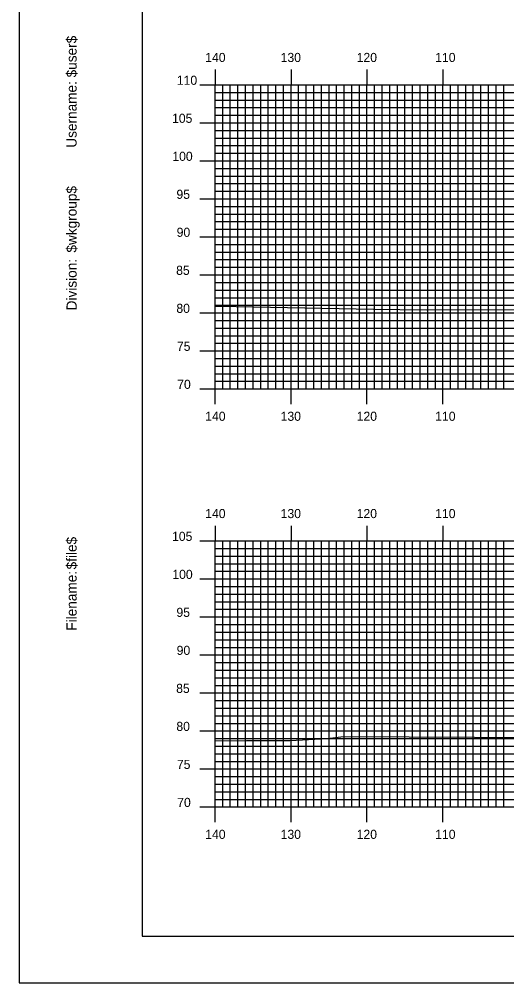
# Model space of a CAD drawing. Extents: x 1758643 to 1758986, y 442591 to 442811.
# Drawn here: x 1758642.9 to 1758707.1, y 442590.5 to 442717.3 of the extents above; entities that cross this region are included whole.
import ezdxf

# ---------------------------------------------------------------- set-up
doc = ezdxf.new("R2010")
doc.units = 0
for name, color, linetype in [('BORDER', 7, 'Continuous'), ('H_V ANNOTATION', 7, 'Continuous'), ('MAJOR', 7, 'Continuous'), ('MINOR', 7, 'Continuous'), ('PLOT BOUNDARY', 7, 'Continuous'), ('S_Roadway_Centerline', 7, 'Continuous')]:
    doc.layers.add(name, color=color, linetype=linetype)

msp = doc.modelspace()

# ---------------------------------------------------------------- linework, layer by layer
at = {"layer": 'BORDER'}
msp.add_lwpolyline([(1758659.05, 442596.67), (1758979.05, 442596.67), (1758979.05, 442806.67), (1758659.05, 442806.67)], close=True, dxfattribs=at)
at = {"layer": 'MAJOR'}
for p, q in [((1758668.65, 442710.67), (1758668.65, 442708.67)), ((1758678.65, 442710.67), (1758678.65, 442708.67)), ((1758688.65, 442710.67), (1758688.65, 442708.67)), ((1758698.65, 442710.67), (1758698.65, 442708.67)), ((1758666.64, 442708.67), (1758668.65, 442708.67)), ((1758668.65, 442708.67), (1758948.65, 442708.67)), ((1758668.65, 442668.67), (1758668.65, 442708.67)), ((1758668.65, 442668.67), (1758668.65, 442708.67)), ((1758668.65, 442708.67), (1758948.65, 442708.67)), ((1758678.65, 442668.67), (1758678.65, 442708.67)), ((1758688.65, 442668.67), (1758688.65, 442708.67)), ((1758698.65, 442668.67), (1758698.65, 442708.67)), ((1758666.64, 442703.67), (1758668.65, 442703.67)), ((1758668.65, 442703.67), (1758948.65, 442703.67)), ((1758666.64, 442698.67), (1758668.65, 442698.67)), ((1758668.65, 442698.67), (1758948.65, 442698.67)), ((1758666.64, 442693.67), (1758668.65, 442693.67)), ((1758668.65, 442693.67), (1758948.65, 442693.67)), ((1758666.64, 442688.67), (1758668.65, 442688.67)), ((1758668.65, 442688.67), (1758948.65, 442688.67)), ((1758666.64, 442683.67), (1758668.65, 442683.67)), ((1758668.65, 442683.67), (1758948.65, 442683.67)), ((1758666.64, 442678.67), (1758668.65, 442678.67)), ((1758668.65, 442678.67), (1758948.65, 442678.67)), ((1758666.64, 442673.67), (1758668.65, 442673.67)), ((1758668.65, 442673.67), (1758948.65, 442673.67)), ((1758666.64, 442668.67), (1758668.65, 442668.67)), ((1758668.65, 442668.67), (1758948.65, 442668.67)), ((1758668.65, 442668.67), (1758948.65, 442668.67)), ((1758668.65, 442666.66), (1758668.65, 442668.67)), ((1758678.65, 442666.66), (1758678.65, 442668.67)), ((1758688.65, 442666.66), (1758688.65, 442668.67)), ((1758698.65, 442666.66), (1758698.65, 442668.67)), ((1758668.65, 442650.67), (1758668.65, 442648.67)), ((1758678.65, 442650.67), (1758678.65, 442648.67)), ((1758688.65, 442650.67), (1758688.65, 442648.67)), ((1758698.65, 442650.67), (1758698.65, 442648.67)), ((1758666.64, 442648.67), (1758668.65, 442648.67)), ((1758668.65, 442648.67), (1758948.65, 442648.67)), ((1758668.65, 442613.67), (1758668.65, 442648.67)), ((1758668.65, 442613.67), (1758668.65, 442648.67)), ((1758668.65, 442648.67), (1758948.65, 442648.67)), ((1758678.65, 442613.67), (1758678.65, 442648.67)), ((1758688.65, 442613.67), (1758688.65, 442648.67)), ((1758698.65, 442613.67), (1758698.65, 442648.67)), ((1758666.64, 442643.67), (1758668.65, 442643.67)), ((1758668.65, 442643.67), (1758948.65, 442643.67)), ((1758666.64, 442638.67), (1758668.65, 442638.67)), ((1758668.65, 442638.67), (1758948.65, 442638.67)), ((1758666.64, 442633.67), (1758668.65, 442633.67)), ((1758668.65, 442633.67), (1758948.65, 442633.67)), ((1758666.64, 442628.67), (1758668.65, 442628.67)), ((1758668.65, 442628.67), (1758948.65, 442628.67)), ((1758666.64, 442623.67), (1758668.65, 442623.67)), ((1758668.65, 442623.67), (1758948.65, 442623.67)), ((1758666.64, 442618.67), (1758668.65, 442618.67)), ((1758668.65, 442618.67), (1758948.65, 442618.67)), ((1758666.64, 442613.67), (1758668.65, 442613.67)), ((1758668.65, 442613.67), (1758948.65, 442613.67)), ((1758668.65, 442613.67), (1758948.65, 442613.67)), ((1758668.65, 442611.66), (1758668.65, 442613.67)), ((1758678.65, 442611.66), (1758678.65, 442613.67)), ((1758688.65, 442611.66), (1758688.65, 442613.67)), ((1758698.65, 442611.66), (1758698.65, 442613.67))]:
    msp.add_line(p, q, dxfattribs=at)
at = {"layer": 'MINOR'}
for p, q in [((1758669.65, 442668.67), (1758669.65, 442708.67)), ((1758670.65, 442668.67), (1758670.65, 442708.67)), ((1758671.65, 442668.67), (1758671.65, 442708.67)), ((1758672.65, 442668.67), (1758672.65, 442708.67)), ((1758673.65, 442668.67), (1758673.65, 442708.67)), ((1758674.65, 442668.67), (1758674.65, 442708.67)), ((1758675.65, 442668.67), (1758675.65, 442708.67)), ((1758676.65, 442668.67), (1758676.65, 442708.67)), ((1758677.65, 442668.67), (1758677.65, 442708.67)), ((1758679.65, 442668.67), (1758679.65, 442708.67)), ((1758680.65, 442668.67), (1758680.65, 442708.67)), ((1758681.65, 442668.67), (1758681.65, 442708.67)), ((1758682.65, 442668.67), (1758682.65, 442708.67)), ((1758683.65, 442668.67), (1758683.65, 442708.67)), ((1758684.65, 442668.67), (1758684.65, 442708.67)), ((1758685.65, 442668.67), (1758685.65, 442708.67)), ((1758686.65, 442668.67), (1758686.65, 442708.67)), ((1758687.65, 442668.67), (1758687.65, 442708.67)), ((1758689.65, 442668.67), (1758689.65, 442708.67)), ((1758690.65, 442668.67), (1758690.65, 442708.67)), ((1758691.65, 442668.67), (1758691.65, 442708.67)), ((1758692.65, 442668.67), (1758692.65, 442708.67)), ((1758693.65, 442668.67), (1758693.65, 442708.67)), ((1758694.65, 442668.67), (1758694.65, 442708.67)), ((1758695.65, 442668.67), (1758695.65, 442708.67)), ((1758696.65, 442668.67), (1758696.65, 442708.67)), ((1758697.65, 442668.67), (1758697.65, 442708.67)), ((1758699.65, 442668.67), (1758699.65, 442708.67)), ((1758700.65, 442668.67), (1758700.65, 442708.67)), ((1758701.65, 442668.67), (1758701.65, 442708.67)), ((1758702.65, 442668.67), (1758702.65, 442708.67)), ((1758703.65, 442668.67), (1758703.65, 442708.67)), ((1758704.65, 442668.67), (1758704.65, 442708.67)), ((1758705.65, 442668.67), (1758705.65, 442708.67)), ((1758706.65, 442668.67), (1758706.65, 442708.67)), ((1758668.65, 442707.67), (1758948.65, 442707.67)), ((1758668.65, 442707.67), (1758670.65, 442707.67)), ((1758668.65, 442706.67), (1758948.65, 442706.67)), ((1758668.65, 442706.67), (1758670.65, 442706.67)), ((1758668.65, 442705.67), (1758948.65, 442705.67)), ((1758668.65, 442705.67), (1758670.65, 442705.67)), ((1758668.65, 442704.67), (1758948.65, 442704.67)), ((1758668.65, 442704.67), (1758670.65, 442704.67)), ((1758668.65, 442702.67), (1758948.65, 442702.67)), ((1758668.65, 442702.67), (1758670.65, 442702.67)), ((1758668.65, 442701.67), (1758948.65, 442701.67)), ((1758668.65, 442701.67), (1758670.65, 442701.67)), ((1758668.65, 442700.67), (1758948.65, 442700.67)), ((1758668.65, 442700.67), (1758670.65, 442700.67)), ((1758668.65, 442699.67), (1758948.65, 442699.67)), ((1758668.65, 442699.67), (1758670.65, 442699.67)), ((1758668.65, 442697.67), (1758948.65, 442697.67)), ((1758668.65, 442697.67), (1758670.65, 442697.67)), ((1758668.65, 442696.67), (1758948.65, 442696.67)), ((1758668.65, 442696.67), (1758670.65, 442696.67)), ((1758668.65, 442695.67), (1758948.65, 442695.67)), ((1758668.65, 442695.67), (1758670.65, 442695.67)), ((1758668.65, 442694.67), (1758948.65, 442694.67)), ((1758668.65, 442694.67), (1758670.65, 442694.67)), ((1758668.65, 442692.67), (1758948.65, 442692.67)), ((1758668.65, 442692.67), (1758670.65, 442692.67)), ((1758668.65, 442691.67), (1758948.65, 442691.67)), ((1758668.65, 442691.67), (1758670.65, 442691.67)), ((1758668.65, 442690.67), (1758948.65, 442690.67)), ((1758668.65, 442690.67), (1758670.65, 442690.67)), ((1758668.65, 442689.67), (1758948.65, 442689.67)), ((1758668.65, 442689.67), (1758670.65, 442689.67)), ((1758668.65, 442687.67), (1758948.65, 442687.67)), ((1758668.65, 442687.67), (1758670.65, 442687.67)), ((1758668.65, 442686.67), (1758948.65, 442686.67)), ((1758668.65, 442686.67), (1758670.65, 442686.67)), ((1758668.65, 442685.67), (1758948.65, 442685.67)), ((1758668.65, 442685.67), (1758670.65, 442685.67)), ((1758668.65, 442684.67), (1758948.65, 442684.67)), ((1758668.65, 442684.67), (1758670.65, 442684.67)), ((1758668.65, 442682.67), (1758948.65, 442682.67)), ((1758668.65, 442682.67), (1758670.65, 442682.67)), ((1758668.65, 442681.67), (1758948.65, 442681.67)), ((1758668.65, 442681.67), (1758670.65, 442681.67)), ((1758668.65, 442680.67), (1758948.65, 442680.67)), ((1758668.65, 442680.67), (1758670.65, 442680.67)), ((1758668.65, 442679.67), (1758948.65, 442679.67)), ((1758668.65, 442679.67), (1758670.65, 442679.67)), ((1758668.65, 442677.67), (1758948.65, 442677.67)), ((1758668.65, 442677.67), (1758670.65, 442677.67)), ((1758668.65, 442676.67), (1758948.65, 442676.67)), ((1758668.65, 442676.67), (1758670.65, 442676.67)), ((1758668.65, 442675.67), (1758948.65, 442675.67)), ((1758668.65, 442675.67), (1758670.65, 442675.67)), ((1758668.65, 442674.67), (1758948.65, 442674.67)), ((1758668.65, 442674.67), (1758670.65, 442674.67)), ((1758668.65, 442672.67), (1758948.65, 442672.67)), ((1758668.65, 442672.67), (1758670.65, 442672.67)), ((1758668.65, 442671.67), (1758948.65, 442671.67)), ((1758668.65, 442671.67), (1758670.65, 442671.67)), ((1758668.65, 442670.67), (1758948.65, 442670.67)), ((1758668.65, 442670.67), (1758670.65, 442670.67)), ((1758668.65, 442669.67), (1758948.65, 442669.67)), ((1758668.65, 442669.67), (1758670.65, 442669.67)), ((1758669.65, 442613.67), (1758669.65, 442648.67)), ((1758670.65, 442613.67), (1758670.65, 442648.67)), ((1758671.65, 442613.67), (1758671.65, 442648.67)), ((1758672.65, 442613.67), (1758672.65, 442648.67)), ((1758673.65, 442613.67), (1758673.65, 442648.67)), ((1758674.65, 442613.67), (1758674.65, 442648.67)), ((1758675.65, 442613.67), (1758675.65, 442648.67)), ((1758676.65, 442613.67), (1758676.65, 442648.67)), ((1758677.65, 442613.67), (1758677.65, 442648.67)), ((1758679.65, 442613.67), (1758679.65, 442648.67)), ((1758680.65, 442613.67), (1758680.65, 442648.67)), ((1758681.65, 442613.67), (1758681.65, 442648.67)), ((1758682.65, 442613.67), (1758682.65, 442648.67)), ((1758683.65, 442613.67), (1758683.65, 442648.67)), ((1758684.65, 442613.67), (1758684.65, 442648.67)), ((1758685.65, 442613.67), (1758685.65, 442648.67)), ((1758686.65, 442613.67), (1758686.65, 442648.67)), ((1758687.65, 442613.67), (1758687.65, 442648.67)), ((1758689.65, 442613.67), (1758689.65, 442648.67)), ((1758690.65, 442613.67), (1758690.65, 442648.67)), ((1758691.65, 442613.67), (1758691.65, 442648.67)), ((1758692.65, 442613.67), (1758692.65, 442648.67)), ((1758693.65, 442613.67), (1758693.65, 442648.67)), ((1758694.65, 442613.67), (1758694.65, 442648.67)), ((1758695.65, 442613.67), (1758695.65, 442648.67)), ((1758696.65, 442613.67), (1758696.65, 442648.67)), ((1758697.65, 442613.67), (1758697.65, 442648.67)), ((1758699.65, 442613.67), (1758699.65, 442648.67)), ((1758700.65, 442613.67), (1758700.65, 442648.67)), ((1758701.65, 442613.67), (1758701.65, 442648.67)), ((1758702.65, 442613.67), (1758702.65, 442648.67)), ((1758703.65, 442613.67), (1758703.65, 442648.67)), ((1758704.65, 442613.67), (1758704.65, 442648.67)), ((1758705.65, 442613.67), (1758705.65, 442648.67)), ((1758706.65, 442613.67), (1758706.65, 442648.67)), ((1758668.65, 442647.67), (1758948.65, 442647.67)), ((1758668.65, 442647.67), (1758670.65, 442647.67)), ((1758668.65, 442646.67), (1758948.65, 442646.67)), ((1758668.65, 442646.67), (1758670.65, 442646.67)), ((1758668.65, 442645.67), (1758948.65, 442645.67)), ((1758668.65, 442645.67), (1758670.65, 442645.67)), ((1758668.65, 442644.67), (1758948.65, 442644.67)), ((1758668.65, 442644.67), (1758670.65, 442644.67)), ((1758668.65, 442642.67), (1758948.65, 442642.67)), ((1758668.65, 442642.67), (1758670.65, 442642.67)), ((1758668.65, 442641.67), (1758948.65, 442641.67)), ((1758668.65, 442641.67), (1758670.65, 442641.67)), ((1758668.65, 442640.67), (1758948.65, 442640.67)), ((1758668.65, 442640.67), (1758670.65, 442640.67)), ((1758668.65, 442639.67), (1758948.65, 442639.67)), ((1758668.65, 442639.67), (1758670.65, 442639.67)), ((1758668.65, 442637.67), (1758948.65, 442637.67)), ((1758668.65, 442637.67), (1758670.65, 442637.67)), ((1758668.65, 442636.67), (1758948.65, 442636.67)), ((1758668.65, 442636.67), (1758670.65, 442636.67)), ((1758668.65, 442635.67), (1758948.65, 442635.67)), ((1758668.65, 442635.67), (1758670.65, 442635.67)), ((1758668.65, 442634.67), (1758948.65, 442634.67)), ((1758668.65, 442634.67), (1758670.65, 442634.67)), ((1758668.65, 442632.67), (1758948.65, 442632.67)), ((1758668.65, 442632.67), (1758670.65, 442632.67)), ((1758668.65, 442631.67), (1758948.65, 442631.67)), ((1758668.65, 442631.67), (1758670.65, 442631.67)), ((1758668.65, 442630.67), (1758948.65, 442630.67)), ((1758668.65, 442630.67), (1758670.65, 442630.67)), ((1758668.65, 442629.67), (1758948.65, 442629.67)), ((1758668.65, 442629.67), (1758670.65, 442629.67)), ((1758668.65, 442627.67), (1758948.65, 442627.67)), ((1758668.65, 442627.67), (1758670.65, 442627.67)), ((1758668.65, 442626.67), (1758948.65, 442626.67)), ((1758668.65, 442626.67), (1758670.65, 442626.67)), ((1758668.65, 442625.67), (1758948.65, 442625.67)), ((1758668.65, 442625.67), (1758670.65, 442625.67)), ((1758668.65, 442624.67), (1758948.65, 442624.67)), ((1758668.65, 442624.67), (1758670.65, 442624.67)), ((1758668.65, 442622.67), (1758948.65, 442622.67)), ((1758668.65, 442622.67), (1758670.65, 442622.67)), ((1758668.65, 442621.67), (1758948.65, 442621.67)), ((1758668.65, 442621.67), (1758670.65, 442621.67)), ((1758668.65, 442620.67), (1758948.65, 442620.67)), ((1758668.65, 442620.67), (1758670.65, 442620.67)), ((1758668.65, 442619.67), (1758948.65, 442619.67)), ((1758668.65, 442619.67), (1758670.65, 442619.67)), ((1758668.65, 442617.67), (1758948.65, 442617.67)), ((1758668.65, 442617.67), (1758670.65, 442617.67)), ((1758668.65, 442616.67), (1758948.65, 442616.67)), ((1758668.65, 442616.67), (1758670.65, 442616.67)), ((1758668.65, 442615.67), (1758948.65, 442615.67)), ((1758668.65, 442615.67), (1758670.65, 442615.67)), ((1758668.65, 442614.67), (1758948.65, 442614.67)), ((1758668.65, 442614.67), (1758670.65, 442614.67))]:
    msp.add_line(p, q, dxfattribs=at)
at = {"layer": 'PLOT BOUNDARY'}
msp.add_lwpolyline([(1758642.86, 442590.55), (1758982.86, 442590.55), (1758982.86, 442810.55), (1758642.86, 442810.55)], close=True, dxfattribs=at)
at = {"layer": 'S_Roadway_Centerline'}
for points in [[(1758668.65, 442679.55), (1758669.14, 442679.55), (1758689.52, 442679.16), (1758696.42, 442679.09), (1758711.78, 442679.13), (1758713.91, 442679.19), (1758726.74, 442679.3), (1758732.65, 442679.27), (1758732.97, 442679.14), (1758735.85, 442678.72), (1758741.57, 442678.82), (1758743.51, 442678.99), (1758745.78, 442679.24), (1758751.32, 442679.36), (1758752.54, 442679.39), (1758758, 442679.38), (1758774.87, 442679.33)], [(1758668.65, 442622.36), (1758672.79, 442622.4), (1758678.47, 442622.41), (1758683.44, 442622.69), (1758685.54, 442622.94), (1758711.43, 442622.82), (1758711.56, 442622.82), (1758711.97, 442622.88), (1758718.44, 442623.75), (1758719.15, 442623.78), (1758720.3, 442623.9), (1758723.42, 442624.1), (1758733.59, 442623.99), (1758735.4, 442623.93), (1758735.74, 442623.95), (1758735.91, 442623.92), (1758736.14, 442623.97), (1758738.31, 442623.96), (1758748.42, 442624.13), (1758749.19, 442624.5), (1758752.27, 442624.44), (1758762.94, 442625.29), (1758767.94, 442625.41), (1758774.37, 442625.17)]]:
    msp.add_lwpolyline(points, dxfattribs=at)

# ---------------------------------------------------------------- texts
at = {"layer": 'BORDER'}
for s, p in [('$user$', (1758650.42, 442709.65)), ('$user$', (1758650.42, 442709.65)), ('Username:', (1758650.42, 442700.4)), ('Username:', (1758650.42, 442700.4)), ('$wkgroup$', (1758650.42, 442686.6)), ('$wkgroup$', (1758650.42, 442686.6)), ('Division:', (1758650.42, 442679)), ('Division:', (1758650.42, 442679)), ('$file$', (1758650.42, 442644.92)), ('$file$', (1758650.42, 442644.92)), ('Filename:', (1758650.42, 442636.86)), ('Filename:', (1758650.42, 442636.86))]:
    msp.add_text(s, height=1.339, rotation=90, dxfattribs=at).set_placement(p)
at = {"layer": 'H_V ANNOTATION'}
for s, p in [('140', (1758667.35, 442711.67)), ('130', (1758677.28, 442711.67)), ('120', (1758687.29, 442711.67)), ('110', (1758697.63, 442711.67)), ('110', (1758663.61, 442708.67)), ('105', (1758662.98, 442703.67)), ('100', (1758663.02, 442698.67)), ('95', (1758663.56, 442693.67)), ('90', (1758663.59, 442688.67)), ('85', (1758663.52, 442683.67)), ('80', (1758663.55, 442678.67)), ('75', (1758663.62, 442673.67)), ('70', (1758663.66, 442668.67)), ('140', (1758667.35, 442664.47)), ('130', (1758677.28, 442664.47)), ('120', (1758687.29, 442664.47)), ('110', (1758697.63, 442664.47)), ('140', (1758667.35, 442651.67)), ('130', (1758677.28, 442651.67)), ('120', (1758687.29, 442651.67)), ('110', (1758697.63, 442651.67)), ('105', (1758662.98, 442648.67)), ('100', (1758663.02, 442643.67)), ('95', (1758663.56, 442638.67)), ('90', (1758663.59, 442633.67)), ('85', (1758663.52, 442628.67)), ('80', (1758663.55, 442623.67)), ('75', (1758663.62, 442618.67)), ('70', (1758663.66, 442613.67)), ('140', (1758667.35, 442609.47)), ('130', (1758677.28, 442609.47)), ('120', (1758687.29, 442609.47)), ('110', (1758697.63, 442609.47))]:
    msp.add_text(s, height=1.2, dxfattribs=at).set_placement(p)
at = {"layer": 'MAJOR'}
for p in [(1758668.64, 442668.67), (1758668.64, 442613.67)]:
    msp.add_text('-', height=0.012, dxfattribs=at).set_placement(p)

doc.saveas('drawing.dxf')
